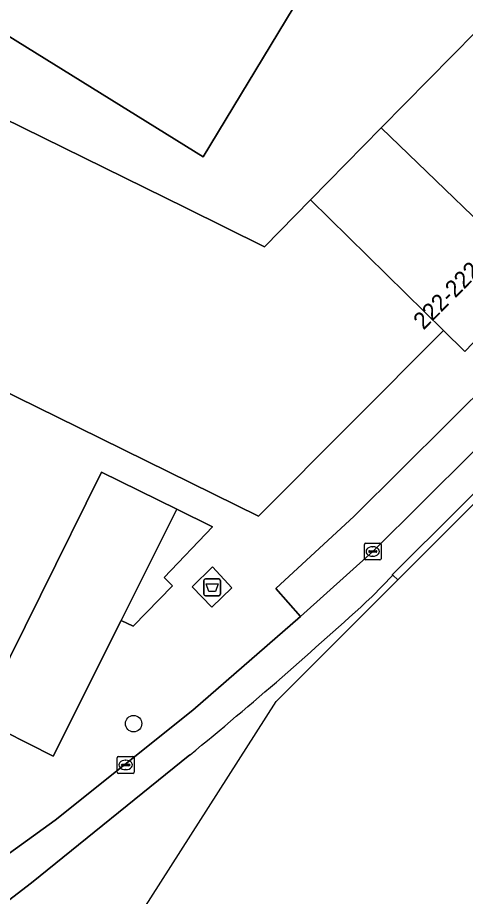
# Model space of a CAD drawing. Extents: x 160102 to 160934, y 382045 to 382923.
# Drawn here: x 160371.6 to 160398.2, y 382092.9 to 382145.1 of the extents above; entities that cross this region are included whole.
import ezdxf

# ---------------------------------------------------------------- set-up
doc = ezdxf.new("R2010")
doc.units = 0
for name, color, linetype in [('IMGEO_Afval_apart_plaats', 7, 'Continuous'), ('IMGEO_Boom', 7, 'Continuous'), ('IMGEO_Erf', 7, 'Continuous'), ('IMGEO_Groenvoorziening', 7, 'Continuous'), ('IMGEO_Kolk', 7, 'Continuous'), ('IMGEO_Pand', 7, 'Continuous'), ('IMGEO_Pand_nummerreeks', 7, 'Continuous'), ('IMGEO_Parkeervlak_open', 7, 'Continuous'), ('IMGEO_Rijbaan_lokaal_gesloten', 7, 'Continuous'), ('IMGEO_Rijbaan_lokaal_open', 7, 'Continuous'), ('IMGEO_Voetpad_gesloten', 7, 'Continuous'), ('IMGEO_Voetpad_open', 7, 'Continuous')]:
    doc.layers.add(name, color=color, linetype=linetype)

msp = doc.modelspace()

# ---------------------------------------------------------------- linework, layer by layer
at = {"layer": 'IMGEO_Afval_apart_plaats'}
for p, q in [((160382.653, 382110.88), (160382.653, 382111.68)), ((160382.653, 382111.68), (160382.653, 382110.88)), ((160382.753, 382111.78), (160383.543, 382111.78)), ((160383.543, 382111.78), (160382.753, 382111.78)), ((160383.643, 382111.68), (160383.643, 382110.88)), ((160383.643, 382110.88), (160383.643, 382111.68)), ((160383.543, 382110.78), (160382.753, 382110.78)), ((160382.753, 382110.78), (160383.543, 382110.78))]:
    msp.add_line(p, q, dxfattribs=at)
msp.add_lwpolyline([(160382.796, 382111.494), (160383.5, 382111.494), (160383.351, 382111.024), (160382.945, 382111.024), (160382.796, 382111.494)], dxfattribs=at)
for centre, start, end in [((160382.753, 382111.68), 90, 180), ((160382.753, 382111.68), 90, 180), ((160383.543, 382111.68), 0, 90), ((160383.543, 382111.68), 360, 90), ((160382.753, 382110.88), 180, 270), ((160382.753, 382110.88), 180, 270), ((160383.543, 382110.88), 270, 0), ((160383.543, 382110.88), 270, 0)]:
    msp.add_arc(centre, 0.1, start, end, dxfattribs=at)
at = {"layer": 'IMGEO_Boom'}
msp.add_circle((160378.48, 382103.175), 0.489, dxfattribs=at)
at = {"layer": 'IMGEO_Erf'}
for points in [[(160390.641, 382150.148), (160382.622, 382136.868), (160360.97, 382150.296)], [(160338.652, 382109.851), (160352.794, 382102.932), (160354.16, 382105.584), (160350.361, 382107.46), (160352.488, 382111.804), (160356.312, 382109.931), (160357.245, 382111.877), (160352.759, 382114.083), (160348.686, 382116.085), (160355.637, 382130.221), (160355.172, 382130.45), (160357.94, 382136.079), (160358.469, 382135.819), (160362.182, 382143.369), (160381.585, 382133.827), (160386.261, 382131.527), (160389.009, 382134.32), (160393.204, 382138.582), (160398.835, 382144.303)]]:
    msp.add_lwpolyline(points, dxfattribs=at)
at = {"layer": 'IMGEO_Groenvoorziening'}
msp.add_lwpolyline([(160383.181, 382114.864), (160381.045, 382115.925), (160377.737, 382109.299), (160378.45, 382108.965), (160380.801, 382111.375), (160380.3, 382111.862)], close=True, dxfattribs=at)
at = {"layer": 'IMGEO_Kolk'}
for p, q in [((160392.278, 382113.906), (160393.13, 382113.906)), ((160392.203, 382112.98), (160392.203, 382113.832)), ((160392.462, 382113.4), (160392.462, 382113.412)), ((160392.9, 382113.363), (160392.502, 382113.363)), ((160392.505, 382113.449), (160392.903, 382113.449)), ((160392.691, 382113.686), (160392.716, 382113.686)), ((160392.946, 382113.412), (160392.946, 382113.4)), ((160393.204, 382113.832), (160393.204, 382112.98)), ((160393.13, 382112.906), (160392.278, 382112.906)), ((160392.714, 382113.126), (160392.689, 382113.126)), ((160377.507, 382100.292), (160377.507, 382101.144)), ((160377.582, 382101.218), (160378.434, 382101.218)), ((160377.995, 382100.998), (160378.02, 382100.998)), ((160378.508, 382101.144), (160378.508, 382100.292)), ((160377.766, 382100.712), (160377.766, 382100.724)), ((160378.204, 382100.675), (160377.806, 382100.675)), ((160377.809, 382100.761), (160378.207, 382100.761)), ((160378.018, 382100.438), (160377.993, 382100.438)), ((160378.25, 382100.724), (160378.25, 382100.712)), ((160378.434, 382100.218), (160377.582, 382100.218))]:
    msp.add_line(p, q, dxfattribs=at)
for points in [[(160392.278, 382113.906), (160393.13, 382113.906)], [(160392.203, 382112.98), (160392.203, 382113.832)], [(160393.204, 382113.832), (160393.204, 382112.98)], [(160393.13, 382112.906), (160392.278, 382112.906)], [(160377.507, 382100.292), (160377.507, 382101.144)], [(160377.582, 382101.218), (160378.434, 382101.218)], [(160378.508, 382101.144), (160378.508, 382100.292)], [(160378.434, 382100.218), (160377.582, 382100.218)]]:
    msp.add_lwpolyline(points, dxfattribs=at)
for centre, radius, start, end in [((160392.28, 382113.83), 0.0765, 91.552, 178.448), ((160392.28, 382113.83), 0.0765, 91.552, 178.448), ((160393.128, 382113.83), 0.0765, 1.552, 88.448), ((160393.128, 382113.83), 0.0765, 1.552, 88.448), ((160392.502, 382113.409), 0.0403, 85.8775, 175.7526), ((160392.499, 382113.399), 0.0366, 178.938, 274.7102), ((160392.903, 382113.406), 0.043, 264.8664, 352.4533), ((160392.907, 382113.411), 0.0386, 1.7309, 96.639), ((160392.28, 382112.982), 0.0765, 181.552, 268.448), ((160392.28, 382112.982), 0.0765, 181.552, 268.448), ((160393.128, 382112.982), 0.0765, 271.552, 358.448), ((160393.128, 382112.982), 0.0765, 271.552, 358.448), ((160377.584, 382101.142), 0.0765, 91.552, 178.448), ((160377.584, 382101.142), 0.0765, 91.552, 178.448), ((160378.432, 382101.142), 0.0765, 1.552, 88.448), ((160378.432, 382101.142), 0.0765, 1.552, 88.448), ((160377.584, 382100.294), 0.0765, 181.552, 268.448), ((160377.584, 382100.294), 0.0765, 181.552, 268.448), ((160377.806, 382100.721), 0.0403, 85.8775, 175.7526), ((160377.803, 382100.711), 0.0366, 178.938, 274.7102), ((160378.207, 382100.718), 0.043, 264.8664, 352.4533), ((160378.211, 382100.723), 0.0386, 1.7309, 96.639), ((160378.432, 382100.294), 0.0765, 271.552, 358.448), ((160378.432, 382100.294), 0.0765, 271.552, 358.448)]:
    msp.add_arc(centre, radius, start, end, dxfattribs=at)
for centre, major_axis, ratio, start_param, end_param in [((160392.69, 382113.406), (-0.387, 0.002), 0.722429, 4.712389, 7.853982), ((160392.715, 382113.406), (-0.39, 0.002), 0.717154, 1.570796, 4.712389), ((160377.994, 382100.718), (-0.387, 0.002), 0.722429, 4.712389, 7.853982), ((160378.019, 382100.718), (-0.39, 0.002), 0.717154, 1.570796, 4.712389)]:
    msp.add_ellipse(centre, major_axis=major_axis, ratio=ratio, start_param=start_param, end_param=end_param, dxfattribs=at)
at = {"layer": 'IMGEO_Pand'}
for points in [[(160375.944, 382161.47), (160373.951, 382162.715), (160371.097, 382164.499), (160370.486, 382164.881), (160368.08, 382166.384), (160361.059, 382170.772), (160351.722, 382156.031), (160360.97, 382150.296), (160382.622, 382136.868), (160390.641, 382150.148), (160392.289, 382149.06), (160393.273, 382150.638), (160396.38, 382155.619), (160393.822, 382157.424), (160390.828, 382152.168), (160388.341, 382153.722), (160387.662, 382154.146), (160385.934, 382155.226), (160385.243, 382155.658), (160381.371, 382158.078)], [(160393.204, 382138.582), (160402.418, 382129.716), (160407.983, 382135.5), (160398.835, 382144.303)], [(160389.009, 382134.32), (160386.261, 382131.527), (160381.585, 382133.827), (160362.182, 382143.369), (160358.469, 382135.819), (160357.94, 382136.079), (160355.172, 382130.45), (160355.637, 382130.221), (160348.686, 382116.085), (160352.759, 382114.083), (160357.245, 382111.877), (160364.265, 382126.152), (160375.199, 382120.775), (160385.904, 382115.51), (160396.915, 382126.54)], [(160402.418, 382129.716), (160393.204, 382138.582), (160389.009, 382134.32), (160396.915, 382126.54), (160398.172, 382125.303)]]:
    msp.add_lwpolyline(points, close=True, dxfattribs=at)
at = {"layer": 'IMGEO_Parkeervlak_open'}
for points in [[(160401.568, 382122.206), (160399.989, 382123.834), (160391.605, 382115.497), (160386.948, 382111.211), (160388.404, 382109.546), (160392.704, 382113.406)], [(160377.737, 382109.299), (160381.045, 382115.925), (160376.568, 382118.128), (160369.295, 382103.465), (160373.701, 382101.235)]]:
    msp.add_lwpolyline(points, close=True, dxfattribs=at)
at = {"layer": 'IMGEO_Rijbaan_lokaal_gesloten'}
for points in [[(160450.854, 382168.735), (160475.495, 382195.521), (160478.755, 382199.065), (160464.564, 382184.907), (160462.855, 382183.211), (160458.173, 382178.567), (160443.127, 382163.591), (160441.429, 382161.899), (160435.263, 382155.752), (160431.547, 382152.051), (160425.387, 382145.918), (160412.659, 382133.242), (160411.386, 382131.974), (160402.865, 382123.493), (160401.568, 382122.206), (160392.704, 382113.406), (160388.404, 382109.546), (160382.002, 382103.966), (160373.822, 382097.426), (160365.435, 382091.385), (160363.786, 382090.244), (160365.528, 382088.435), (160372.418, 382093.703), (160381.834, 382101.318)], [(160392.646, 382110.713), (160393.9, 382111.993), (160393.866, 382112.025), (160429.946, 382147.939), (160445.076, 382162.993), (160450.854, 382168.735)], [(160394.184, 382111.721), (160393.9, 382111.993), (160392.646, 382110.713)], [(160358.645, 382065.208), (160358.455, 382064.907), (160360.836, 382063.609), (160386.959, 382104.494), (160394.184, 382111.721)], [(160381.834, 382101.318), (160372.418, 382093.703), (160365.528, 382088.435)]]:
    msp.add_lwpolyline(points, dxfattribs=at)
msp.add_arc((160223, 382295.027), 250.503, 309.35045, 312.62704, dxfattribs=at)
msp.add_arc((160223, 382295.027), 250.503, 309.35045, 312.62704, dxfattribs=at)
at = {"layer": 'IMGEO_Rijbaan_lokaal_open'}
msp.add_lwpolyline([(160394.184, 382111.721), (160430.168, 382147.718), (160429.946, 382147.939), (160393.866, 382112.025), (160393.9, 382111.993)], close=True, dxfattribs=at)
at = {"layer": 'IMGEO_Voetpad_gesloten'}
msp.add_lwpolyline([(160383.165, 382112.492), (160381.969, 382111.306), (160383.132, 382110.091), (160384.329, 382111.25)], close=True, dxfattribs=at)
at = {"layer": 'IMGEO_Voetpad_open'}
for points in [[(160430.554, 382158.76), (160429.817, 382156.626), (160414.457, 382140.689), (160413.69, 382141.431), (160407.983, 382135.5), (160402.418, 382129.716), (160398.172, 382125.303), (160396.915, 382126.54), (160385.904, 382115.51), (160375.199, 382120.775), (160364.265, 382126.152), (160357.245, 382111.877), (160356.312, 382109.931), (160354.16, 382105.584), (160352.794, 382102.932), (160344.903, 382086.804), (160342.736, 382079.526)], [(160391.605, 382115.497), (160399.989, 382123.834), (160401.568, 382122.206), (160402.865, 382123.493), (160401.257, 382125.124), (160409.776, 382133.584), (160411.386, 382131.974), (160412.659, 382133.242), (160411.053, 382134.853), (160423.831, 382147.506), (160425.387, 382145.918), (160431.547, 382152.051), (160431.237, 382152.379)], [(160349.662, 382081.225), (160361.551, 382088.699), (160363.786, 382090.244), (160365.435, 382091.385), (160373.822, 382097.426), (160382.002, 382103.966), (160388.404, 382109.546), (160386.948, 382111.211), (160391.605, 382115.497)]]:
    msp.add_lwpolyline(points, dxfattribs=at)
for points in [[(160376.568, 382118.128), (160381.045, 382115.925), (160383.181, 382114.864), (160380.3, 382111.862), (160380.801, 382111.375), (160378.45, 382108.965), (160377.737, 382109.299), (160373.701, 382101.235), (160369.295, 382103.465)], [(160383.165, 382112.492), (160384.329, 382111.25), (160383.132, 382110.091), (160381.969, 382111.306)]]:
    msp.add_lwpolyline(points, close=True, dxfattribs=at)

# ---------------------------------------------------------------- texts
at = {"layer": 'IMGEO_Pand_nummerreeks'}
msp.add_text('222-222A', height=1, rotation=45.2357, dxfattribs=at).set_placement((160395.722, 382126.542))

doc.saveas('drawing.dxf')
